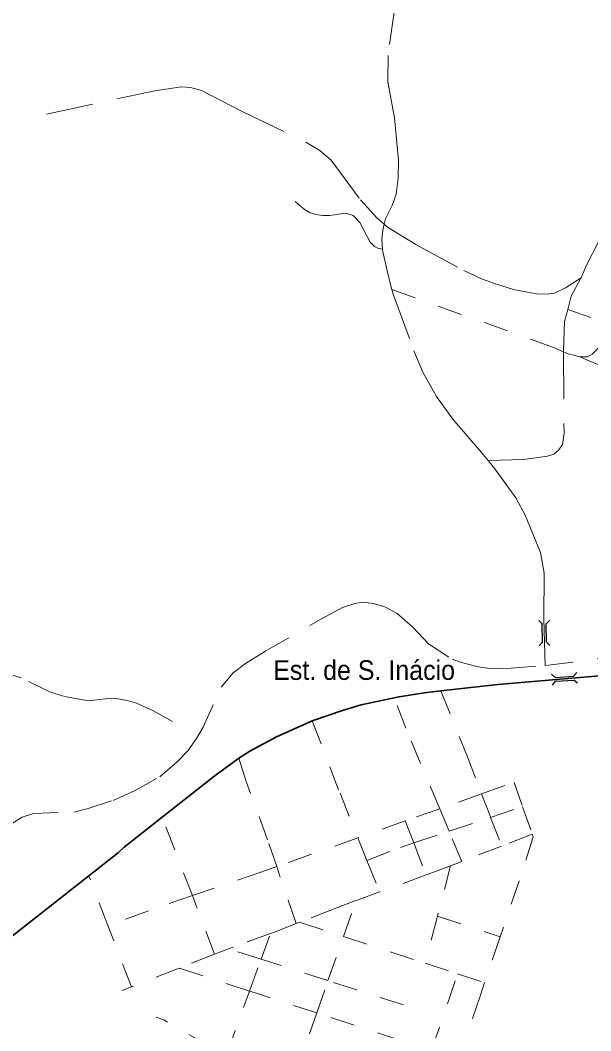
# Model space of a CAD drawing. Extents: x 783.4 to 809.8, y 7536.4 to 7564.6.
# Drawn here: x 798.152 to 800.475, y 7556.106 to 7560.221 of the extents above; entities that cross this region are included whole.
import ezdxf
from ezdxf.enums import TextEntityAlignment as Align

# ---------------------------------------------------------------- set-up
doc = ezdxf.new("R2010")
doc.units = 0
doc.header["$LTSCALE"] = 0.032
for name, pattern in [('DOTTED', [1.5, 0.3, -1.2]), ('LONG_DASHED', [7.5, 6, -1.5]), ('MEDIUM_DASHED', [4.5, 3, -1.5])]:
    doc.linetypes.add(name, pattern=pattern)
for name, color, linetype, lineweight in [('10', 7, 'Continuous', 25), ('18', 7, 'DOTTED', 13), ('2', 7, 'Continuous', 35), ('5', 7, 'LONG_DASHED', 13), ('6', 7, 'MEDIUM_DASHED', 13), ('7', 7, 'DOTTED', 13)]:
    doc.layers.add(name, color=color, linetype=linetype, lineweight=lineweight)
doc.layers.add('61', color=7, linetype='Continuous')

msp = doc.modelspace()

# ---------------------------------------------------------------- linework, layer by layer
at = {"layer": '10'}
for p, q in [((800.3067, 7557.7771), (800.2929, 7557.7627)), ((800.2942, 7557.6887), (800.2929, 7557.7627)), ((800.2782, 7557.6885), (800.2642, 7557.6742)), ((800.3085, 7557.675), (800.2942, 7557.6887)), ((800.3301, 7557.545), (800.3152, 7557.5581)), ((800.3182, 7557.514), (800.3312, 7557.529)), ((800.3312, 7557.529), (800.4051, 7557.5342)), ((800.4202, 7557.5211), (800.4051, 7557.5342))]:
    msp.add_line(p, q, dxfattribs=at)
for points in [[(800.2782, 7557.6885), (800.2769, 7557.7625), (800.2625, 7557.7764)], [(800.3301, 7557.545), (800.4039, 7557.5501), (800.4171, 7557.5652)]]:
    msp.add_lwpolyline(points, dxfattribs=at)
at = {"layer": '18'}
for points in [[(798.1052, 7556.9424), (798.1603, 7556.9753), (798.2065, 7556.9911), (798.3704, 7556.9963), (798.4285, 7557.0104), (798.5307, 7557.0442), (798.6199, 7557.0846), (798.7206, 7557.1405), (798.7908, 7557.2007), (798.8339, 7557.2458), (798.8689, 7557.2956), (798.897, 7557.3426), (798.9697, 7557.5047), (799.0188, 7557.5629), (799.0689, 7557.6015), (799.1581, 7557.6569), (799.3761, 7557.7823), (799.4643, 7557.8293), (799.5144, 7557.8462), (799.5455, 7557.8509), (799.5906, 7557.8462), (799.6367, 7557.8321), (799.6868, 7557.8058), (799.7494, 7557.7508), (799.8136, 7557.6822), (799.9098, 7557.6193), (799.9479, 7557.6052), (800.016, 7557.5883), (800.0631, 7557.5817), (800.1508, 7557.5822), (800.2891, 7557.5934)], [(800.2891, 7557.5934), (800.3021, 7557.5944), (800.5617, 7557.6291)]]:
    msp.add_lwpolyline(points, dxfattribs=at)
at = {"layer": '2'}
for points in [[(799.8641, 7557.4896), (800.0959, 7557.5156), (800.5884, 7557.5585)], [(799.3409, 7557.3679), (799.4636, 7557.4108), (799.5404, 7557.4332), (799.6746, 7557.4619)], [(799.6746, 7557.4619), (799.694, 7557.466), (799.7964, 7557.482), (799.8641, 7557.4896)], [(799.0423, 7557.2156), (799.086, 7557.2444), (799.1948, 7557.3036), (799.3356, 7557.366), (799.3409, 7557.3679)], [(798.7296, 7556.9756), (798.9452, 7557.146), (799.0252, 7557.2044), (799.0423, 7557.2156)], [(798.4312, 7556.7372), (798.5524, 7556.8324), (798.5748, 7556.8532), (798.7296, 7556.9756)], [(797.7039, 7556.1648), (797.8531, 7556.2828), (797.8571, 7556.2828), (797.8587, 7556.2876), (798.4312, 7556.7372)]]:
    msp.add_lwpolyline(points, dxfattribs=at)
at = {"layer": '5'}
for points in [[(799.6819, 7560.3127), (799.6496, 7560.0781), (799.6486, 7559.9701), (799.6752, 7559.824), (799.6912, 7559.6511), (799.6907, 7559.5783), (799.6827, 7559.5134), (799.6656, 7559.4664), (799.6386, 7559.4129), (799.6334, 7559.391)], [(798.2593, 7559.8392), (798.6998, 7559.9341), (798.8083, 7559.9496), (798.8454, 7559.9469), (798.8905, 7559.9355), (799.0523, 7559.8509), (799.3149, 7559.725), (799.371, 7559.6912), (799.4176, 7559.6513), (799.5374, 7559.4897), (799.6036, 7559.4164), (799.6334, 7559.391)], [(799.6334, 7559.391), (799.6276, 7559.3668), (799.6236, 7559.3302), (799.6268, 7559.2886)], [(799.6334, 7559.391), (799.6477, 7559.3788), (799.7629, 7559.3074), (799.9578, 7559.2017), (800.029, 7559.1688), (800.0861, 7559.1472), (800.1593, 7559.1246), (800.2538, 7559.1069), (800.2944, 7559.1055), (800.3265, 7559.1102), (800.3716, 7559.1309), (800.4347, 7559.1727)], [(800.5143, 7559.3329), (800.5076, 7559.3221), (800.4568, 7559.2233), (800.4347, 7559.1727)], [(799.6268, 7559.2886), (799.6271, 7559.2846), (799.6492, 7559.1831), (799.6649, 7559.1248)], [(800.4347, 7559.1727), (800.4338, 7559.1706), (800.3947, 7559.0973), (800.3805, 7559.0435)], [(799.6649, 7559.1248), (799.6702, 7559.1051), (799.7539, 7558.8754), (799.791, 7558.788), (799.8471, 7558.6893), (799.9127, 7558.5967), (800.03, 7558.4614), (800.0562, 7558.4288)], [(800.3805, 7559.0435), (800.3676, 7558.9949), (800.3631, 7558.8741), (800.3631, 7558.8712)], [(800.3631, 7558.8712), (800.3656, 7558.5382), (800.3596, 7558.4931), (800.3446, 7558.4715), (800.3245, 7558.4546), (800.2985, 7558.4461), (800.2022, 7558.432), (800.0562, 7558.4288)], [(800.0562, 7558.4288), (800.0881, 7558.3891), (800.1698, 7558.2759), (800.2068, 7558.2057), (800.2704, 7558.053), (800.2845, 7557.9694), (800.283, 7557.7837), (800.2891, 7557.5934)]]:
    msp.add_lwpolyline(points, dxfattribs=at)
at = {"layer": '6'}
msp.add_lwpolyline([(798.7717, 7557.3658), (798.6923, 7557.4108), (798.6252, 7557.4396), (798.5876, 7557.4508), (798.55, 7557.4572), (798.5084, 7557.4588), (798.4308, 7557.45), (798.3276, 7557.4684), (798.2756, 7557.4844), (798.1564, 7557.5428), (798.1124, 7557.5572)], dxfattribs=at)
at = {"layer": '7'}
for p, q in [((800.3805, 7559.0435), (800.554, 7558.9826)), ((800.0301, 7557.0707), (799.8595, 7557.0101)), ((800.0301, 7557.0707), (800.0667, 7556.9749)), ((799.8595, 7557.0101), (799.7191, 7556.9602)), ((799.8979, 7556.9186), (799.8595, 7557.0101)), ((800.0667, 7556.9749), (800.1969, 7557.0183)), ((800.1969, 7557.0183), (800.2361, 7556.9064)), ((799.8979, 7556.9186), (800.0667, 7556.9749)), ((800.0667, 7556.9749), (800.1113, 7556.8582)), ((799.7191, 7556.9602), (799.5266, 7556.8918)), ((799.7191, 7556.9602), (799.7539, 7556.8706)), ((799.5266, 7556.8918), (799.1961, 7556.7743)), ((799.5266, 7556.8918), (799.5635, 7556.7997)), ((799.7539, 7556.8706), (799.8979, 7556.9186)), ((800.2361, 7556.9064), (800.1113, 7556.8582)), ((799.7539, 7556.8706), (799.8043, 7556.7405)), ((799.2754, 7556.5425), (799.1961, 7556.7743)), ((799.5635, 7556.7997), (799.6151, 7556.6711)), ((799.9036, 7556.7781), (799.8503, 7556.5723)), ((799.9496, 7556.7958), (799.9036, 7556.7781)), ((798.5091, 7556.5339), (798.4312, 7556.7372)), ((799.6151, 7556.6711), (799.5186, 7556.6357)), ((799.4674, 7556.4891), (799.5186, 7556.6357)), ((799.8503, 7556.5723), (799.8007, 7556.3806)), ((799.8503, 7556.5723), (800.1056, 7556.488)), ((798.6046, 7556.2848), (798.5091, 7556.5339)), ((799.2882, 7556.5475), (799.4674, 7556.4891)), ((799.1326, 7556.3972), (799.1704, 7556.5016)), ((799.4048, 7556.3099), (799.4674, 7556.4891)), ((799.4674, 7556.4891), (799.8007, 7556.3806)), ((800.1056, 7556.488), (800.0425, 7556.3019)), ((799.0001, 7556.4397), (798.9428, 7556.4172)), ((799.1326, 7556.3972), (799.0001, 7556.4397)), ((798.9428, 7556.4172), (798.7987, 7556.3608)), ((799.0857, 7556.2675), (799.1326, 7556.3972)), ((799.4048, 7556.3099), (799.1326, 7556.3972)), ((799.0857, 7556.2675), (798.7987, 7556.3608)), ((799.8007, 7556.3806), (799.9325, 7556.3377)), ((799.3589, 7556.1783), (799.4048, 7556.3099)), ((799.7127, 7556.2112), (799.4048, 7556.3099)), ((799.9325, 7556.3377), (800.0425, 7556.3019)), ((798.9933, 7556.0125), (799.0857, 7556.2675)), ((799.2631, 7555.9042), (799.3589, 7556.1783))]:
    msp.add_line(p, q, dxfattribs=at)
for points in [[(799.271, 7559.4834), (799.3086, 7559.4507), (799.3301, 7559.4387), (799.3549, 7559.4299), (799.3844, 7559.4255), (799.4126, 7559.4255), (799.4677, 7559.4337), (799.4852, 7559.4324), (799.5073, 7559.4255), (799.5349, 7559.397), (799.5764, 7559.3177), (799.5942, 7559.3003), (799.6076, 7559.2927), (799.6268, 7559.2886)], [(799.6649, 7559.1248), (800.3222, 7558.889), (800.3631, 7558.8712)], [(800.43, 7558.8505), (800.4606, 7558.8504), (800.4807, 7558.8611), (800.5065, 7558.8867), (800.5381, 7558.9392), (800.554, 7558.9826)], [(800.3631, 7558.8712), (800.3819, 7558.863), (800.4055, 7558.8568), (800.43, 7558.8505)], [(800.43, 7558.8505), (800.6807, 7558.7422), (800.6841, 7558.7409)], [(799.8595, 7557.0101), (799.7217, 7557.3377), (799.6746, 7557.4619)], [(799.8641, 7557.4896), (799.9697, 7557.2289), (800.0301, 7557.0707)], [(799.3409, 7557.3679), (799.4539, 7557.0729), (799.5266, 7556.8918)], [(799.1961, 7556.7743), (799.1585, 7556.8841), (799.0715, 7557.1216), (799.0423, 7557.2156)], [(800.0301, 7557.0707), (800.162, 7557.1176), (800.1969, 7557.0183)], [(799.1961, 7556.7743), (799.1308, 7556.7511), (798.8531, 7556.6561), (798.7296, 7556.9756)], [(800.1113, 7556.8582), (799.9496, 7556.7958), (799.8979, 7556.9186)], [(800.2361, 7556.9064), (800.2399, 7556.8957), (800.1831, 7556.7168), (800.1056, 7556.488)], [(799.5635, 7556.7997), (799.6996, 7556.8525), (799.7539, 7556.8706)], [(799.9036, 7556.7781), (799.8423, 7556.7544), (799.8043, 7556.7405), (799.6151, 7556.6711)], [(798.8531, 7556.6561), (798.674, 7556.5948), (798.5091, 7556.5339)], [(798.9428, 7556.4172), (798.8601, 7556.6379), (798.8531, 7556.6561)], [(799.5186, 7556.6357), (799.4293, 7556.603), (799.2882, 7556.5475), (799.2754, 7556.5425)], [(799.2754, 7556.5425), (799.1829, 7556.5061), (799.1704, 7556.5016)], [(799.1704, 7556.5016), (799.0183, 7556.4468), (799.0001, 7556.4397)], [(798.7987, 7556.3608), (798.6046, 7556.2848), (798.5667, 7556.2699)], [(799.6737, 7555.5744), (799.8266, 7556.0255), (799.9325, 7556.3377)], [(799.3589, 7556.1783), (799.1181, 7556.257), (799.0857, 7556.2675)], [(800.0425, 7556.3019), (800.0251, 7556.2507), (799.71, 7555.2979), (799.6668, 7555.1755)], [(798.9933, 7556.0125), (798.9249, 7556.0411), (798.7372, 7556.1498), (798.706, 7556.1617)], [(799.8266, 7556.0255), (799.7017, 7556.0663), (799.3589, 7556.1783)]]:
    msp.add_lwpolyline(points, dxfattribs=at)

# ---------------------------------------------------------------- texts
at = {"layer": '61', "width": 0.95}
msp.add_text('Est. de S. Inácio', height=0.08, dxfattribs=at).set_placement((799.9218, 7557.5348), align=Align.RIGHT)

doc.saveas('drawing.dxf')
